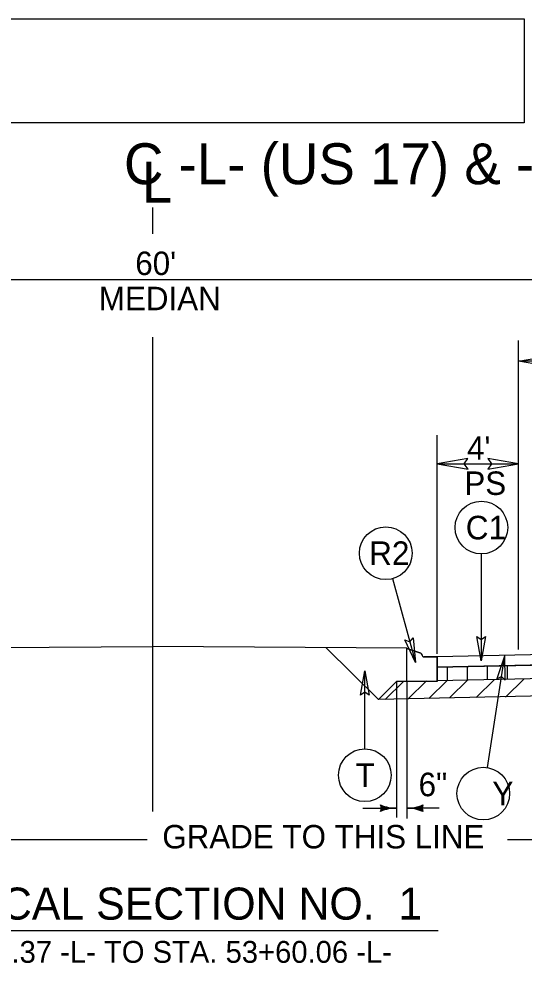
# Model space of a CAD drawing. Extents: x 2176024 to 2177225, y 75947 to 76635.
# Drawn here: x 2176769.25 to 2176794.12, y 76538.35 to 76584.79 of the extents above; entities that cross this region are included whole.
import ezdxf

# ---------------------------------------------------------------- set-up
doc = ezdxf.new("R2010")
doc.units = 0
for name, color, linetype in [('Old_Level_1', 7, 'Continuous'), ('Old_Level_11', 7, 'Continuous'), ('Old_Level_3', 7, 'Continuous'), ('Prop Dimension', 7, 'Continuous'), ('Prop Pavement Schedule Description CELL', 7, 'Continuous'), ('Typical Curb CELL', 7, 'Continuous'), ('Typical Pavement Slope CELL', 7, 'Continuous'), ('Typical Shoulder Slope CELL', 7, 'Continuous'), ('Typical Slope Point Local CELL', 7, 'Continuous'), ('Typical Terminator CELL', 7, 'Continuous'), ('Typical Text General CELL', 7, 'Continuous'), ('Typical Text Label CELL', 7, 'Continuous')]:
    doc.layers.add(name, color=color, linetype=linetype)

msp = doc.modelspace()

# ---------------------------------------------------------------- linework, layer by layer
at = {"layer": 'Old_Level_1'}
for p, q in [((2176788.341, 76552.203), (2176788.341, 76553.828)), ((2176788.341, 76553.828), (2176789.027, 76553.599)), ((2176789.091, 76553.51), (2176789.091, 76553.505)), ((2176789.185, 76553.411), (2176789.841, 76553.411)), ((2176789.841, 76553.411), (2176789.841, 76552.203)), ((2176790.341, 76552.244), (2176790.347, 76552.916)), ((2176791.326, 76552.268), (2176791.331, 76552.936)), ((2176792.315, 76552.284), (2176792.32, 76552.957)), ((2176793.298, 76552.303), (2176793.303, 76552.977)), ((2176787.284, 76551.315), (2176788.185, 76552.201)), ((2176789.841, 76552.203), (2176788.341, 76552.203)), ((2176788.403, 76551.338), (2176789.304, 76552.224)), ((2176789.43, 76551.361), (2176790.329, 76552.246)), ((2176790.46, 76551.414), (2176791.331, 76552.27)), ((2176791.749, 76551.404), (2176792.654, 76552.294)), ((2176793.197, 76551.426), (2176794.115, 76552.329)), ((2176762.567, 76539.958), (2176789.888, 76539.958))]:
    msp.add_line(p, q, dxfattribs=at)
for centre, start, end in [((2176788.997, 76553.51), 0, 71.5651), ((2176789.185, 76553.505), 180, 270)]:
    msp.add_arc(centre, 0.0937, start, end, dxfattribs=at)
at = {"layer": 'Old_Level_11'}
for p, q in [((2176792.006, 76558.471), (2176792.006, 76553.209)), ((2176787.645, 76557.257), (2176788.768, 76553.139)), ((2176792.307, 76547.965), (2176793.167, 76553.487)), ((2176786.277, 76548.884), (2176786.277, 76552.726)), ((2176787.841, 76552.194), (2176787.841, 76545.508)), ((2176788.341, 76552.204), (2176788.341, 76545.466)), ((2176786.174, 76545.97), (2176787.841, 76545.97)), ((2176789.941, 76545.966), (2176788.341, 76545.966))]:
    msp.add_line(p, q, dxfattribs=at)
for points in [[(2176788.656, 76554.351), (2176788.768, 76553.139), (2176788.248, 76554.248), (2176788.494, 76554.156)], [(2176792.213, 76554.409), (2176792.006, 76553.209), (2176791.793, 76554.415), (2176792.006, 76554.262)], [(2176793.187, 76552.269), (2176793.167, 76553.487), (2176792.771, 76552.328), (2176793.005, 76552.446)], [(2176786.07, 76551.526), (2176786.277, 76552.726), (2176786.49, 76551.519), (2176786.277, 76551.673)]]:
    msp.add_lwpolyline(points, close=True, dxfattribs=at)
for centre in [(2176792.012, 76559.767), (2176787.305, 76558.508), (2176786.277, 76547.588), (2176792.108, 76546.684)]:
    msp.add_circle(centre, 1.296, dxfattribs=at)
for centre, radius, start, end in [((2176786.633, 76545.97), 0.448, 339.2343, 20.766), ((2176787.816, 76547.885), 1.915, 246.4848, 270.7622), ((2176787.816, 76544.054), 1.915, 89.2381, 113.5155), ((2176787.816, 76547.885), 1.942, 247.1893, 260.4638), ((2176787.816, 76544.054), 1.942, 99.5365, 112.811), ((2176787.816, 76547.885), 1.969, 247.7696, 256.6115), ((2176787.816, 76544.054), 1.969, 103.3888, 112.2307), ((2176787.816, 76547.885), 1.995, 248.2502, 253.7031), ((2176787.816, 76544.054), 1.995, 106.2972, 111.7501), ((2176787.816, 76547.885), 2.022, 248.6472, 251.2913), ((2176787.816, 76544.054), 2.022, 108.709, 111.3531), ((2176788.367, 76547.881), 1.915, 269.2382, 293.5156), ((2176788.367, 76544.051), 1.915, 66.4849, 90.7623), ((2176788.367, 76547.881), 1.942, 279.5367, 292.8111), ((2176788.367, 76544.051), 1.942, 67.1895, 80.4639), ((2176788.367, 76547.881), 1.969, 283.389, 292.2308), ((2176788.367, 76544.051), 1.969, 67.7698, 76.6116), ((2176788.367, 76547.881), 1.995, 286.2973, 291.7503), ((2176788.367, 76544.051), 1.995, 68.2503, 73.7032), ((2176788.367, 76547.881), 2.022, 288.7091, 291.3532), ((2176788.367, 76544.051), 2.022, 68.6473, 71.2914), ((2176789.55, 76545.966), 0.448, 159.2344, 200.7661)]:
    msp.add_arc(centre, radius, start, end, dxfattribs=at)
at = {"layer": 'Prop Dimension'}
for p, q in [((2176775.841, 76574.219), (2176775.841, 76575.512)), ((2176805.841, 76571.958), (2176745.841, 76571.958)), ((2176775.841, 76545.809), (2176775.841, 76569.127)), ((2176793.841, 76553.767), (2176793.841, 76568.966)), ((2176805.841, 76567.947), (2176793.841, 76567.947)), ((2176789.841, 76553.564), (2176789.841, 76564.317)), ((2176789.841, 76562.904), (2176793.841, 76562.904)), ((2176761.143, 76544.435), (2176775.557, 76544.435)), ((2176793.298, 76544.435), (2176800.129, 76544.435))]:
    msp.add_line(p, q, dxfattribs=at)
at = {"layer": 'Prop Pavement Schedule Description CELL'}
msp.add_lwpolyline([(2176730.689, 76579.671), (2176725.575, 76579.671), (2176725.575, 76584.785), (2176794.118, 76584.785), (2176794.118, 76579.671), (2176730.689, 76579.671), (2176730.689, 76584.785)], dxfattribs=at)
at = {"layer": 'Typical Curb CELL'}
for p, q in [((2176788.341, 76552.203), (2176788.341, 76553.828)), ((2176789.027, 76553.599), (2176788.341, 76553.828)), ((2176789.091, 76553.505), (2176789.091, 76553.511)), ((2176789.841, 76553.411), (2176789.185, 76553.411)), ((2176789.841, 76552.203), (2176789.841, 76553.411)), ((2176789.841, 76552.203), (2176788.341, 76552.203))]:
    msp.add_line(p, q, dxfattribs=at)
for centre, start, end in [((2176788.997, 76553.51), 0, 71.5651), ((2176789.185, 76553.505), 180, 270)]:
    msp.add_arc(centre, 0.0937, start, end, dxfattribs=at)
at = {"layer": 'Typical Pavement Slope CELL'}
for p, q in [((2176763.341, 76553.834), (2176775.841, 76553.918)), ((2176788.341, 76553.834), (2176775.841, 76553.918)), ((2176784.377, 76553.861), (2176786.947, 76551.305)), ((2176805.345, 76553.228), (2176789.841, 76552.905)), ((2176787.841, 76552.194), (2176786.947, 76551.305)), ((2176788.341, 76552.204), (2176787.841, 76552.194)), ((2176805.841, 76551.737), (2176786.947, 76551.305))]:
    msp.add_line(p, q, dxfattribs=at)
at = {"layer": 'Typical Shoulder Slope CELL'}
msp.add_line((2176805.841, 76552.569), (2176789.841, 76552.236), dxfattribs=at)
at = {"layer": 'Typical Slope Point Local CELL'}
msp.add_lwpolyline([(2176805.12, 76553.736), (2176789.841, 76553.418), (2176789.841, 76552.905), (2176805.345, 76553.228)], dxfattribs=at)
at = {"layer": 'Typical Terminator CELL'}
for points in [[(2176795.35, 76567.687), (2176793.841, 76567.947), (2176795.359, 76568.215), (2176795.166, 76567.947)], [(2176791.35, 76563.164), (2176789.841, 76562.904), (2176791.359, 76562.635), (2176791.166, 76562.904)], [(2176792.331, 76562.644), (2176793.841, 76562.904), (2176792.323, 76563.172), (2176792.516, 76562.904)]]:
    msp.add_lwpolyline(points, close=True, dxfattribs=at)

# ---------------------------------------------------------------- texts
at = {"layer": 'Old_Level_11'}
for s, rotation, p in [('C1', 0.0003, (2176791.243, 76559.187)), ('R2', 0.0003, (2176786.489, 76557.928)), ('T', 359.9997, (2176785.82, 76547.008)), ('6"', 0.0002, (2176788.919, 76546.555)), ('Y', 359.9997, (2176792.552, 76546.104))]:
    msp.add_text(s, height=1.16, rotation=rotation, dxfattribs=at).set_placement(p)
at = {"layer": 'Old_Level_3'}
msp.add_text('TYPICAL SECTION NO.  1', height=1.5766, rotation=0, dxfattribs=at).set_placement((2176763.68, 76540.486))
at = {"layer": 'Typical Text General CELL'}
for s, height, p in [("60'", 1.1533, (2176774.979, 76572.188)), ('MEDIAN', 1.1533, (2176773.186, 76570.458)), ("4'", 1.1533, (2176791.304, 76563.104)), ('PS', 1.1533, (2176791.174, 76561.374)), ('GRADE TO THIS LINE', 1.15334, (2176776.309, 76543.989))]:
    msp.add_text(s, height=height, dxfattribs=at).set_placement(p)
at = {"layer": 'Typical Text Label CELL'}
for s, height, p in [('C -L- (US 17) & -L1- (US 17)', 2.01314, (2176774.42, 76576.654)), ('STA. 29+70.37 -L- TO STA. 53+60.06 -L-', 1.0742, (2176761.26, 76538.363))]:
    msp.add_text(s, height=height, dxfattribs=at).set_placement(p)
msp.add_text('L', height=2.013, rotation=359.9469, dxfattribs=at).set_placement((2176775.298, 76575.752))

doc.saveas('drawing.dxf')
